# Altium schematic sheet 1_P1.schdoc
size 309 x 223 mm; Symbol: Sheet-Symbol_A0; Device: Sheet-Symbol_A0; Company: 嘉立创EDA; Version: V1.0; Page Size: A0; @Project Name: MX无人机; @Page Count: 1; @Update Date: 2025-02-17; @Create Date: 2025-02-13; @Schematic Name: Schematic5; @Page No: 1; @Page Name: P1
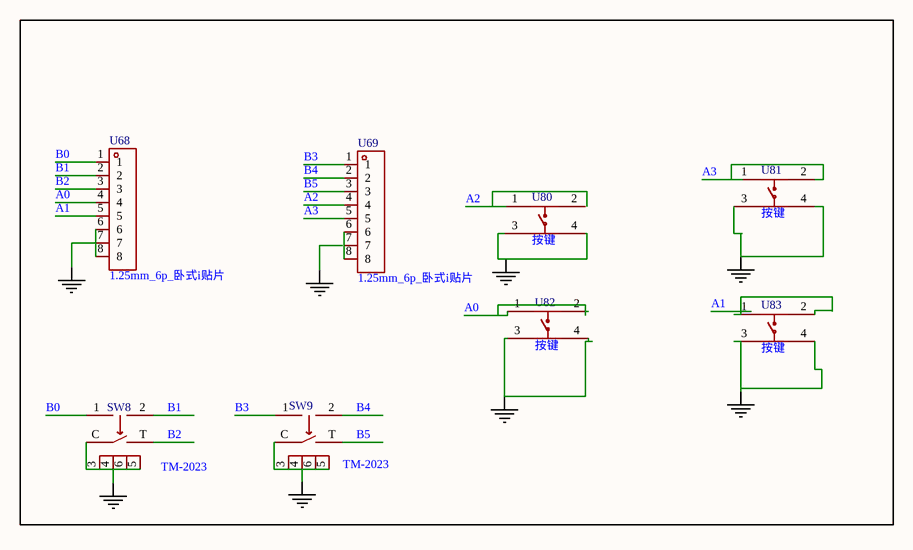
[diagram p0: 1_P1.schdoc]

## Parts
SW8  TM-2023  [SW-SMD_TM-2023-1]
SW9  TM-2023  [SW-SMD_TM-2023-1]
U68  1.25mm_6p_卧式i贴片  [CONN-SMD_6P-P1.25_HC-1.25-6PWT]
U69  1.25mm_6p_卧式i贴片  [CONN-SMD_6P-P1.25_HC-1.25-6PWT]
U80  按键  [SW-SMD_4P-L6.0-W6.0-P4.50-LS9.0-2]
U81  按键  [SW-SMD_4P-L6.0-W6.0-P4.50-LS9.0-2]
U82  按键  [SW-SMD_4P-L6.0-W6.0-P4.50-LS9.0-2]
U83  按键  [SW-SMD_4P-L6.0-W6.0-P4.50-LS9.0-2]

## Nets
GND: SW8.3 SW8.4 SW8.5 SW8.6 SW8.C SW9.3 SW9.4 SW9.5 SW9.6 SW9.C U80.3 U80.4 U81.3 U81.4 U82.3 U82.4 U83.3 U83.4
A0: U68.4 U82.1 U82.2
A1: U68.5 U83.1 U83.2
A2: U69.4 U80.1
A3: U69.5 U81.1 U81.2
B0: SW8.1 U68.1
B1: SW8.2 U68.2
B2: SW8.T U68.3
B3: SW9.1 U69.1
B4: SW9.2 U69.2
B5: SW9.T U69.3
NetU68_6: U68.6 U68.7 U68.8
NetU69_6: U69.6 U69.7 U69.8

Not connected (* = marked no-connect by the designer): U80 2

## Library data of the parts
SW8 SW9 = TM-2023: Manufacturer: XKB Connectivity(中国星坤); Add into BOM: yes
U68 U69 = 1.25mm_6p_卧式i贴片: Symbol: 1.25MM_6P_卧式I贴片_C9900015476; Add into BOM: yes
U80-U83 = 按键: Symbol: SW; Add into BOM: yes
